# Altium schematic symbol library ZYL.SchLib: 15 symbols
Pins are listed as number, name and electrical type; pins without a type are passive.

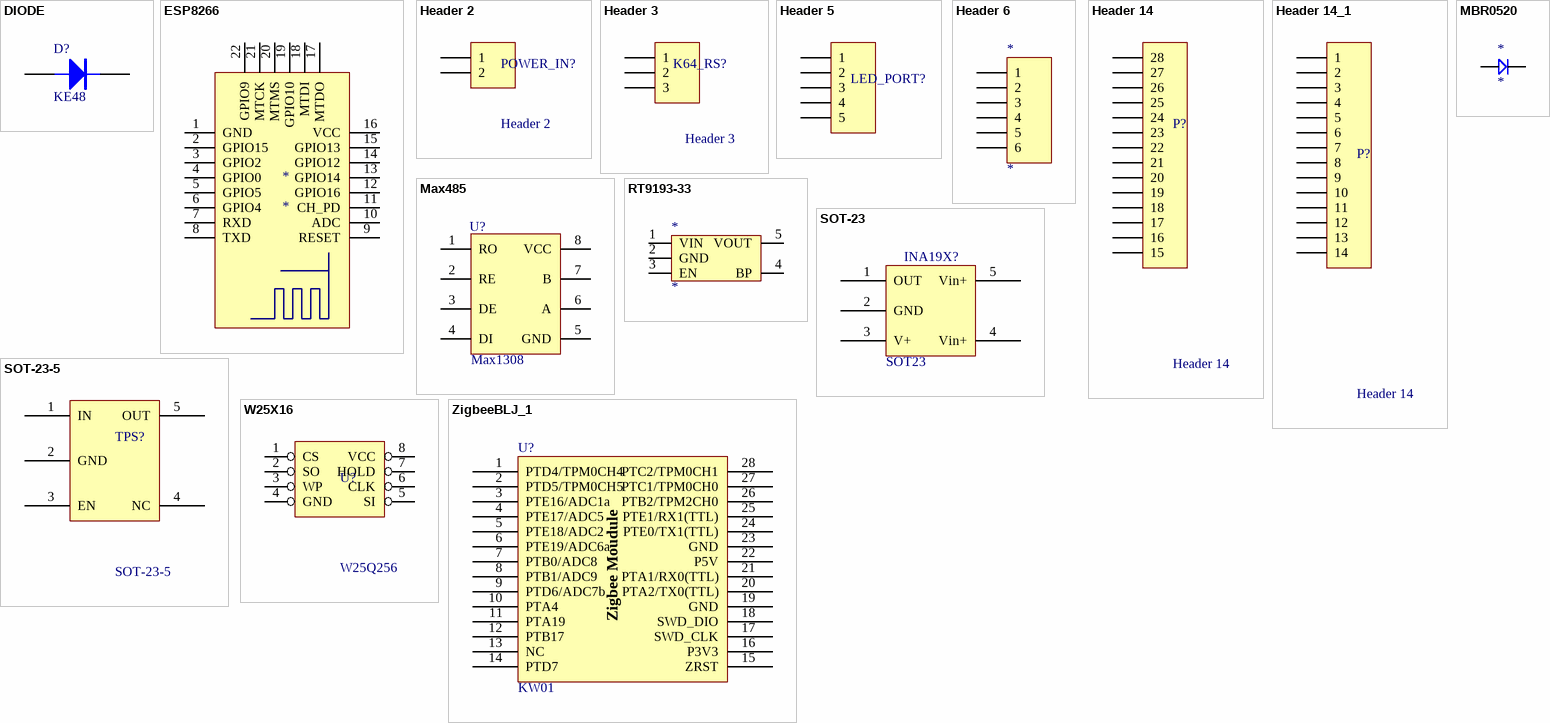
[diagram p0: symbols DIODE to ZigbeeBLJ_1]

## DIODE
designator D?, comment KE48
Diode
footprint SMBJ48A
pins: 1 A, 2 K

## ESP8266
designator *
footprint ESP8266
pins: 1 GND (oe), 2 GPIO15, 3 GPIO2, 4 GPIO0, 5 GPIO5, 6 GPIO4, 7 RXD, 8 TXD, 9 RESET, 10 ADC, 11 CH_PD, 12 GPIO16, 13 GPIO14, 14 GPIO12, 15 GPIO13, 16 VCC, 17 MTDO, 18 MTDI, 19 GPIO10, 20 MTMS, 21 MTCK, 22 GPIO9

## Header 2
designator POWER_IN?
Header, 2-Pin
footprint KF2EGD2
signal-integrity model Connector
pins: 1, 2

## Header 3
designator K64_RS?
Header, 3-Pin
footprint KF2EGD3
signal-integrity model Connector
pins: 1, 2, 3

## Header 5
designator LED_PORT?  (value not drawn)
Header, 5-Pin
footprint KF2EGD5
signal-integrity model Connector
pins: 1, 2, 3, 4, 5

## Header 6
designator *
signal-integrity model Connector
footprint Header 6
pins: 1, 2, 3, 4, 5, 6

## Header 14
designator P?
Header, 14-Pin
footprint HDR1X14 (Connector; Header; 14 Position)
signal-integrity model Connector
pins: 1 28, 2 27, 3 26, 4 25, 5 24, 6 23, 7 22, 8 21, 9 20, 10 19, 11 18, 12 17, 13 16, 14 15

## Header 14_1
designator P?, comment Header 14
Header, 14-Pin
footprint HDR1X14 (Connector; Header; 14 Position)
signal-integrity model Connector
pins: 1, 2, 3, 4, 5, 6, 7, 8, 9, 10, 11, 12, 13, 14

## Max485
designator U?, comment Max1308
footprint DIP-8 (DIP; 8 Leads; Row Spacing 7.62 mm; Pitch 2.54 mm)
footprint SO8
pins: 1 RO, 2 RE, 3 DE, 4 DI, 5 GND, 6 A, 7 B, 8 VCC

## MBR0520
designator *
footprint 1N4148
pins: 1, 2

## RT9193-33
designator *
footprint RT9193-33
pins: 1 VIN, 2 GND, 3 EN, 4 BP, 5 VOUT

## SOT-23
designator INA19X?, comment SOT23
footprint SOT-23-5
pins: 1 OUT, 2 GND, 3 V+, 4 Vin+, 5 Vin+

## SOT-23-5
designator TPS?
footprint SOT-23-5
pins: 1 IN, 2 GND, 3 EN, 4 NC, 5 OUT

## W25X16
designator U?, comment W25Q256
footprint SO8
pins: 1 CS, 2 SO, 3 WP, 4 GND, 5 SI, 6 CLK, 7 HOLD, 8 VCC

## ZigbeeBLJ_1
designator U?, comment KW01
footprint KW01
pins: 1 PTD4/TPM0CH4, 2 PTD5/TPM0CH5, 3 PTE16/ADC1a, 4 PTE17/ADC5, 5 PTE18/ADC2, 6 PTE19/ADC6a, 7 PTB0/ADC8, 8 PTB1/ADC9, 9 PTD6/ADC7b, 10 PTA4, 11 PTA19, 12 PTB17, 13 NC, 14 PTD7, 15 ZRST, 16 P3V3, 17 SWD_CLK, 18 SWD_DIO, 19 GND, 20 PTA2/TX0(TTL), 21 PTA1/RX0(TTL), 22 P5V, 23 GND, 24 PTE0/TX1(TTL), 25 PTE1/RX1(TTL), 26 PTB2/TPM2CH0, 27 PTC1/TPM0CH0, 28 PTC2/TPM0CH1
